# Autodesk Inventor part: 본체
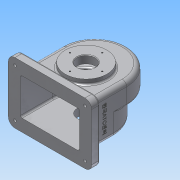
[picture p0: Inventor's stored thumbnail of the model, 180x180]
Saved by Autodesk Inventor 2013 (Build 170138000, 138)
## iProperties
Created: 2017-11
Part Number: 본체
Material: 알루미늄 6061
Document SubType Name: Modeling
Designer: Administrator
Density: 2.71 g/cm^3
Mass: 1079.49 g
Surface Area: 1182.07 cm^2
Volume: 398.335 cm^3
Author: Administrator
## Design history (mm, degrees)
sketch "스케치1"
  geometry: L1 (-58, -65)-(-58, 15); L2 (58, 15)-(58, -65); L3 (58, -65)-(-58, -65); A1 r 58 centre (0, 15) between (58, 15) and (-58, 15); 1 further point
  constraints: 6 end point, 2 perpendicular, 2 point on circle, 1 centre point, 1 tangent, 1 vertical, 1 vertical alignment
  dimensions: "d0" = 116 distance of L2.end L1.start; "d2" = 58 radius of A1; "d3" = 80 vertical distance of L1.start A1.centre; "d5" = 65 vertical distance of point (0, 0) L1.start
extrude "돌출1" new body sketch "스케치1" distance "d6" = 38; taper "d7" = 0 deg
sketch "스케치2"
  geometry: L1 (58, -65)-(58, 15) reference; L2 (-58, 15)-(-58, -65) reference; L3 (-58, -65)-(58, -65) reference; A1 r 58 centre (0, -8) between (58, -8) and (-58, -8); 1 further point
  constraints: 2 point on circle, 2 point on line, 1 centre point
  dimensions: "d9" = 58 radius of A1; "d10" = 57 distance from line of L3 A1.centre
extrude "돌출2" join sketch "스케치2" distance "d11" = 38; taper "d12" = 0 deg
feature "쉘1" dims "d13" = 5
sketch "스케치3"
  geometry: C1 r 37.5 at (0, 0); 1 further point
  constraints: 1 centre point, 1 coincident
  dimensions: "d14" = 37.5 radius of C1
extrude "돌출3" join sketch "스케치3" distance "d15" = 9; taper "d16" = 0 deg
sketch "스케치4"
  geometry: C1 r 31 at (0, 0); 1 further point
  constraints: 2 coincident, 1 centre point
  dimensions: "d17" = 31 radius of C1
extrude "돌출4" join sketch "스케치4" distance "d18" = 10; taper "d19" = 0 deg
sketch "스케치5"
  geometry: L1 (5, -5)-(111, -5) reference; L2 (111, -5)-(111, -71) reference; L3 (111, -71)-(5, -71) reference; L4 (5, -71)-(5, -5) reference; L5 (116, 0)-(0, 0) reference; L6 (0, 0)-(0, -76) reference; L7 (116, -76)-(0, -76) reference; L8 (116, 0)-(116, -76) reference; L9 (133, 17)-(-17, 17); L10 (-17, 17)-(-17, -93); L11 (-17, -93)-(133, -93); L12 (133, -93)-(133, 17); L13 (133, 17)-(-17, -93); L14 (-17, 17)-(133, -93); L15 (0, -38)-(116, -38) reference; 4 further points
  constraints: 12 end point, 4 midpoint, 2 parallel, 1 horizontal, 1 perpendicular, 1 vertical alignment
  dimensions: "d20" = 150 distance of L11.end L10.end; "d21" = 110 distance of L10.end L9.end; "d22" = 55 distance from line of L9.start L15; "d25" = 75 horizontal distance of L9.start point (58, 0)
extrude "돌출5" join sketch "스케치5" distance "d26" = 15; taper "d27" = 0 deg
fillet "모깎기1" dims "d28" = 12
fillet "모깎기2" dims "d29" = 8
fillet "모깎기3" dims "d30" = 3
hole "구멍1" diameter "d33" = 32; stored, may be unused: countersink angle "d37" = 90 deg, drill point angle "d39" = 0 deg; dims "d31" = 10, "d32" = 10, "d34" = 6, "d35" = 4, "d36" = 2, "d38" = 123
chamfer "모따기1" distance "d40" = 1; stored, may be unused: second distance "d41" = 2, angle "d42" = 45 deg
sketch "스케치6"
  geometry: C1 r 37.5 at (0, 0) reference; 1 further point
  constraints: 1 vertical alignment
  dimensions: "d43" = 29 distance of C1.centre point (0, 29)
hole "구멍2" sketch "스케치6" at (0, 29) diameter "d44" = 2.459; stored, may be unused: countersink angle "d48" = 90 deg, drill point angle "d50" = 118 deg; dims "d45" = 6, "d46" = 4, "d47" = 2, "d49" = 8
sketch "스케치7"
  geometry: C1 r 31 at (0, 0) reference; 1 further point
  constraints: 1 vertical alignment
  dimensions: "d51" = 26 distance of point (0, 26) C1.centre
hole "구멍3" sketch "스케치7" at (0, 26) diameter "d52" = 2.459; stored, may be unused: countersink angle "d56" = 90 deg, drill point angle "d58" = 118 deg; dims "d53" = 6, "d54" = 4, "d55" = 2, "d57" = 8
node "작업 평면1"
sketch "스케치8"
  geometry: L1 (13, 93)-(113, 93) reference; C1 r 6 at (63, 74); 2 further points
  constraints: 1 centre point, 1 midpoint, 1 vertical alignment
  dimensions: "d63" = 6 radius of C1; "d64" = 19 distance from line of C1.centre L1
extrude "돌출6" join sketch "스케치8" stored distance "d65" = 15; taper "d66" = 0 deg
hole "구멍4" diameter "d69" = 4.459; stored, may be unused: countersink angle "d73" = 90 deg, drill point angle "d75" = 118 deg; dims "d67" = 10, "d68" = 10, "d70" = 61, "d71" = 4, "d72" = 2, "d74" = 61.75
fillet "모깎기4" dims "d76" = 3
sketch "스케치9" dims "d0" = 116, "d2" = 58, "d3" = 80, "d5" = 65
  geometry: L1 (5, 80)-(5, 18) reference; 3 further points
  constraints: 1 other
  dimensions: "d77" = 40 vertical distance of point (43, 40) point (0, 0); "d78" = 38 distance from line of point (43, 40) L1
feature "엠보싱1" sketch "스케치9" dims "d14" = 37.5, "d79" = 0.5, "d80" = 0
sketch "스케치10"
  geometry: A1 r 9 centre (121, -5) between (121, -14) and (130, -5) reference; A2 r 9 centre (121, 81) between (130, 81) and (121, 90) reference; A3 r 9 centre (-5, 81) between (-5, 90) and (-14, 81) reference; A4 r 9 centre (-5, -5) between (-14, -5) and (-5, -14) reference; 1 further point
hole "구멍5" sketch "스케치10" at (-5, -5), (-5, 81), (121, 81), (121, -5) diameter "d81" = 5; stored, may be unused: countersink angle "d85" = 90 deg, drill point angle "d87" = 118 deg; dims "d82" = 61, "d83" = 12, "d84" = 5, "d86" = 61.75
node "솔리드1"
pattern_circular "원형 패턴1" dims angle "d60" = 360 deg
other parameters: "d62" = -144
